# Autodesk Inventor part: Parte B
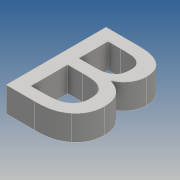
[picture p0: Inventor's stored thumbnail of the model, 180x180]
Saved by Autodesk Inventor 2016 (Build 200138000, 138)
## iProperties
Created: 2015-08
Part Number: Parte B
Material: Generic
Document SubType Name: Modeling
Designer: julian.chica
Density: 1 g/cm^3
Appearance: Default
Author: julian.chica
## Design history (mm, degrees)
sketch "Sketch1"
  geometry: L1 (-8.338, 20.108)-(8.338, 20.108); L2 (8.338, 20.108)-(8.338, 0); L3 (8.338, 0)-(-8.338, 0); L4 (-8.338, 0)-(-8.338, 20.108); 2 further points
  constraints: 1 coincident, 1 midpoint, 2 other
extrude "Extrusion1" new body sketch "Sketch1" distance "d1" = 5; taper "d2" = 0 deg
body "Solid1"
